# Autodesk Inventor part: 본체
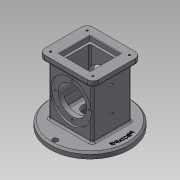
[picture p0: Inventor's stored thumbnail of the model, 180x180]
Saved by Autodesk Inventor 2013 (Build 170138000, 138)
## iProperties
Created: 2019-08
Part Number: 본체
Material: 일반
Document SubType Name: Modeling
Designer: Administrator
Density: 1 g/cm^3
Mass: 384.726 g
Surface Area: 783.782 cm^2
Volume: 384.726 cm^3
Author: Administrator
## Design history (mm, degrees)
sketch "스케치1"
  geometry: C1 r 67.5 at (0, 0); 1 further point
  constraints: 1 centre point, 1 coincident
  dimensions: "d0" = 135 diameter of C1
extrude "돌출1" new body sketch "스케치1" distance "d2" = 10; taper "d3" = 0 deg
sketch "스케치2"
  geometry: L1 (37, -33)-(-37, -33); L2 (-37, -33)-(-37, 33); L3 (-37, 33)-(37, 33); L4 (37, 33)-(37, -33); L5 (37, -33)-(-37, 33); L6 (-37, -33)-(37, 33); C1 r 67.5 at (0, 0) reference
  constraints: 12 end point, 2 midpoint, 2 parallel, 1 horizontal, 1 perpendicular
  dimensions: "d4" = 66 distance of L1.end L2.end; "d6" = 74 distance of L2.end L3.end
extrude "돌출2" join sketch "스케치2" distance "d7" = 98; taper "d8" = 0 deg
sketch "스케치3"
  geometry: L1 (46, -41)-(-46, -41); L2 (-46, -41)-(-46, 41); L3 (-46, 41)-(46, 41); L4 (46, 41)-(46, -41); L5 (46, -41)-(-46, 41); L6 (-46, -41)-(46, 41); 1 further point
  constraints: 12 end point, 2 midpoint, 2 parallel, 1 horizontal, 1 perpendicular
  dimensions: "d9" = 92 distance of L2.end L3.end; "d11" = 82 distance of L3.end L1.start
extrude "돌출3" join sketch "스케치3" distance "d12" = 10; taper "d13" = 0 deg
sketch "스케치4"
  geometry: C1 r 67.5 at (0, 0) reference; C2 r 4.5 at (-59, 0); C3 r 4.5 at (0, 59); C4 r 4.5 at (0, -59); A1 r 59 centre (0, 0) between (-59, 0) and (0, 59)
  constraints: 4 centre point, 3 point on circle, 2 equal radius, 2 vertical alignment, 1 coincident, 1 horizontal alignment
  dimensions: "d14" = 118 diameter of A1; "d16" = 9 diameter of C2
extrude "돌출4" cut sketch "스케치4" stored distance "d17" = 0; taper "d18" = 0 deg
sketch "스케치7"
  geometry: L1 (-33, 98)-(-41, 98) reference; L2 (-41, 98)-(-41, 108) reference; L3 (-41, 108)-(41, 108) reference; L4 (41, 108)-(41, 98) reference; L5 (41, 98)-(33, 98) reference; L6 (33, 98)-(33, 10) reference; L7 (33, 10)-(54.5, 10) reference; L8 (54.5, 10)-(54.5, 0) reference; L9 (54.5, 0)-(-54.5, 0) reference; L10 (-54.5, 0)-(-54.5, 10) reference; L11 (-54.5, 10)-(-33, 10) reference; L12 (-33, 10)-(-33, 98) reference; L13 (-67.5, 0)-(-67.5, 10) reference; L14 (-67.5, 10)-(-63.5, 10) reference; L15 (-63.5, 10)-(-63.5, 0) reference; L16 (-63.5, 0)-(-67.5, 0) reference; L17 (67.5, 10)-(67.5, 0) reference; L18 (67.5, 0)-(63.5, 0) reference; L19 (63.5, 0)-(63.5, 10) reference; L20 (63.5, 10)-(67.5, 10) reference; L21 (-33, 54)-(33, 54); L22 (-33, 89)-(-30, 89); L23 (-30, 89)-(-30, 78); L24 (-30, 78)-(30, 78); L25 (30, 78)-(30, 89); L26 (30, 89)-(33, 89); 1 further point
  constraints: 12 end point, 3 parallel, 2 equal length, 2 midpoint, 2 perpendicular, 2 point on line
  dimensions: "d19" = 70 diameter of L22 L21; "d21" = 48 diameter of L24 L21; "d22" = 3 distance of L22.start L22.end
revolve "회전1" sketch "스케치7" stored, may be unused: angle "d23" = 90 deg
sketch "스케치8"
  geometry: L1 (22, -22)-(-22, -22); L2 (-22, -22)-(-22, 22); L3 (-22, 22)-(22, 22); L4 (22, 22)-(22, -22); L5 (22, -22)-(-22, 22); L6 (-22, -22)-(22, 22); 1 further point
  constraints: 12 end point, 2 midpoint, 2 parallel, 2 perpendicular, 1 horizontal
  dimensions: "d24" = 44 distance of L1.end L2.end
extrude "돌출5" cut sketch "스케치8" distance "d26" = 82; taper "d27" = 0 deg
sketch "스케치9"
  geometry: L1 (26, -26)-(-26, -26); L2 (-26, -26)-(-26, 26); L3 (-26, 26)-(26, 26); L4 (26, 26)-(26, -26); L5 (26, -26)-(-26, 26); L6 (-26, -26)-(26, 26); 1 further point
  constraints: 12 end point, 2 midpoint, 2 parallel, 2 perpendicular, 1 horizontal
  dimensions: "d28" = 52 distance of L1.end L2.end
extrude "돌출6" cut sketch "스케치9" distance "d30" = 8; taper "d31" = 0 deg
sketch "스케치10"
  geometry: L1 (0, 0)-(0, 18); L2 (0, 18)-(-25, 18); L3 (-54.5, 0)-(-54.5, 10) reference; L4 (-54.5, 10)-(-33, 10) reference; L5 (-33, 10)-(-33, 19) reference; L6 (-33, 19)-(-30, 19) reference; L7 (-30, 19)-(-30, 30) reference; L8 (-30, 30)-(-22, 30) reference; L9 (30, 30)-(30, 19) reference; L10 (30, 19)-(33, 19) reference; L11 (33, 19)-(33, 10) reference; L12 (33, 10)-(54.5, 10) reference; L13 (54.5, 10)-(54.5, 0) reference; L14 (54.5, 0)-(-54.5, 0) reference; L15 (41, 98)-(33, 98) reference; L16 (33, 98)-(33, 89) reference; L17 (33, 89)-(30, 89) reference; L18 (30, 89)-(30, 78) reference; L19 (30, 78)-(22, 78) reference; L20 (22, 78)-(22, 100) reference; L21 (22, 100)-(26, 100) reference; L22 (26, 100)-(26, 108) reference; L23 (26, 108)-(41, 108) reference; L24 (41, 108)-(41, 98) reference; L25 (-33, 98)-(-41, 98) reference; L26 (-41, 98)-(-41, 108) reference; L27 (-41, 108)-(-26, 108) reference; L28 (-26, 108)-(-26, 100) reference; L29 (-26, 100)-(-22, 100) reference; L30 (-22, 100)-(-22, 78) reference; L31 (-22, 78)-(-30, 78) reference; L32 (-30, 78)-(-30, 89) reference; L33 (-30, 89)-(-33, 89) reference; L34 (-33, 89)-(-33, 98) reference; L35 (-67.5, 0)-(-67.5, 10) reference; L36 (-67.5, 10)-(-63.5, 10) reference; L37 (-63.5, 10)-(-63.5, 0) reference; L38 (-63.5, 0)-(-67.5, 0) reference; L39 (67.5, 10)-(67.5, 0) reference; L40 (67.5, 0)-(63.5, 0) reference; L41 (63.5, 0)-(63.5, 10) reference; L42 (63.5, 10)-(67.5, 10) reference; L43 (-25, 18)-(-25, 0); L44 (-22, 30)-(-22, 26) reference; L45 (-22, 26)-(22, 26) reference; L46 (22, 26)-(22, 30) reference; L47 (22, 30)-(30, 30) reference
  constraints: 6 end point, 2 perpendicular, 1 point on line, 1 vertical
  dimensions: "d32" = 18 distance of L1.start L1.end; "d33" = 50 diameter of L43 L1
revolve "회전2" sketch "스케치10" stored, may be unused: angle "d34" = 90 deg
sketch "스케치11"
  geometry: L1 (-54.5, 0)-(-54.5, 10) reference; L2 (-54.5, 10)-(-33, 10) reference; L3 (-33, 10)-(-33, 19) reference; L4 (-33, 19)-(-30, 19) reference; L5 (-30, 19)-(-30, 30) reference; L6 (-30, 30)-(-22, 30) reference; L7 (-22, 30)-(-22, 26) reference; L8 (-22, 26)-(22, 26) reference; L9 (22, 26)-(22, 30) reference; L10 (22, 30)-(30, 30) reference; L11 (30, 30)-(30, 19) reference; L12 (30, 19)-(33, 19) reference; L13 (33, 19)-(33, 10) reference; L14 (33, 10)-(54.5, 10) reference; L15 (54.5, 10)-(54.5, 0) reference; L16 (54.5, 0)-(25, 0) reference; L17 (25, 0)-(25, 18) reference; L18 (25, 18)-(-25, 18) reference; L19 (-25, 18)-(-25, 0) reference; L20 (-25, 0)-(-54.5, 0) reference; L21 (41, 98)-(33, 98) reference; L22 (33, 98)-(33, 89) reference; L23 (33, 89)-(30, 89) reference; L24 (30, 89)-(30, 78) reference; L25 (30, 78)-(22, 78) reference; L26 (22, 78)-(22, 100) reference; L27 (22, 100)-(26, 100) reference; L28 (26, 100)-(26, 108) reference; L29 (26, 108)-(41, 108) reference; L30 (41, 108)-(41, 98) reference; L31 (-33, 98)-(-41, 98) reference; L32 (-41, 98)-(-41, 108) reference; L33 (-41, 108)-(-26, 108) reference; L34 (-26, 108)-(-26, 100) reference; L35 (-26, 100)-(-22, 100) reference; L36 (-22, 100)-(-22, 78) reference; L37 (-22, 78)-(-30, 78) reference; L38 (-30, 78)-(-30, 89) reference; L39 (-30, 89)-(-33, 89) reference; L40 (-33, 89)-(-33, 98) reference; L41 (-67.5, 0)-(-67.5, 10) reference; L42 (-67.5, 10)-(-63.5, 10) reference; L43 (-63.5, 10)-(-63.5, 0) reference; L44 (-63.5, 0)-(-67.5, 0) reference; L45 (67.5, 10)-(67.5, 0) reference; L46 (67.5, 0)-(63.5, 0) reference; L47 (63.5, 0)-(63.5, 10) reference; L48 (63.5, 10)-(67.5, 10) reference; L49 (0, 0)-(0, 26); L50 (0, 26)-(-12.5, 26); L51 (-12.5, 26)-(-12.5, 0); L52 (-12.5, 0)-(0, 0)
  constraints: 8 end point, 2 perpendicular, 1 midpoint, 1 point on line
  dimensions: "d35" = 25 diameter of L51 L49
revolve "회전3" sketch "스케치11" stored, may be unused: angle "d37" = 90 deg
sketch "스케치12" dims "d38" = 58
  geometry: C1 r 35 at (0, 0) reference; C2 r 24 at (0, 0) reference; 3 further points
  constraints: 2 vertical alignment, 1 coincident, 2 other
hole "구멍1" sketch "스케치12" at (0, 29) diameter "d40" = 3.242; stored, may be unused: countersink angle "d44" = 90 deg, drill point angle "d46" = 118 deg; dims "d41" = 4, "d42" = 4, "d43" = 2, "d45" = 6
sketch "스케치13"
  geometry: L1 (36, -31)-(-36, -31); L2 (-36, -31)-(-36, 31); L3 (-36, 31)-(36, 31); L4 (36, 31)-(36, -31); L5 (36, -31)-(-36, 31); L6 (-36, -31)-(36, 31); 5 further points
  constraints: 12 end point, 4 coincident, 2 midpoint, 2 parallel, 1 horizontal, 1 perpendicular
  dimensions: "d50" = 62 distance of L1.end L2.end; "d52" = 72 distance of L2.end L3.end
hole "구멍2" sketch "스케치13" at (-36, 31), (36, -31), (36, 31), (-36, -31) diameter "d53" = 3.242; stored, may be unused: countersink angle "d57" = 90 deg, drill point angle "d59" = 118 deg; dims "d54" = 4, "d55" = 4, "d56" = 2, "d58" = 6
sketch "스케치14"
  geometry: L1 (0, 89.456)-(10, 89.456) reference; L2 (10, 89.456)-(10, -23.456) reference; L3 (10, -23.456)-(0, -23.456) reference; L4 (0, -23.456)-(0, 0) reference; L5 (0, 0)-(0, 66) reference; L6 (0, 66)-(0, 89.456) reference; L7 (0, 0)-(-88, 0) reference; L8 (-88, 0)-(-88, -8) reference; L9 (-88, -8)-(-98, -8) reference; L10 (-98, -8)-(-98, 0.724) reference; L11 (-98, 74)-(-88, 74) reference; L12 (-88, 74)-(-88, 66) reference; L13 (-88, 66)-(-88, 0) reference; L14 (-88, 66)-(0, 66) reference; L15 (-98, 0.724)-(-92, 0.724) reference; L16 (-92, 3.276)-(-98, 3.276) reference; L17 (-98, 3.276)-(-98, 62.724) reference; L18 (-98, 62.724)-(-92, 62.724) reference; L19 (-92, 65.276)-(-98, 65.276) reference; L20 (-98, 65.276)-(-98, 74) reference; 4 further points
  constraints: 2 horizontal alignment, 2 vertical alignment, 1 midpoint
  dimensions: "d60" = 37 distance from line of L2 point (-27, 33); "d61" = 43 distance of point (-27, 33) point (-70, 33)
hole "구멍3" sketch "스케치14" at (-27, 33), (-70, 33) diameter "d62" = 4.917; stored, may be unused: countersink angle "d66" = 90 deg, drill point angle "d68" = 118 deg; dims "d63" = 4, "d64" = 4, "d65" = 2, "d67" = 30
fillet "모깎기2" dims "d70" = 3
fillet "모깎기3" dims "d71" = 3
fillet "모깎기4" dims "d72" = 10
fillet "모깎기5" dims "d73" = 3
fillet "모깎기6" dims "d74" = 3
chamfer "모따기1" distance "d75" = 1; stored, may be unused: second distance "d76" = 2, angle "d77" = 45 deg
fillet "모깎기7" dims "d78" = 3
fillet "모깎기8" dims "d79" = 3
node "작업 평면1"
fillet "모깎기9" dims "d84" = 3
chamfer "모따기2" distance "d85" = 3; stored, may be unused: second distance "d86" = 2, angle "d87" = 45 deg
sketch "스케치16"
  geometry: C1 r 64.5 at (0, 0) reference; C2 r 59 at (0, 0)
  constraints: 1 centre point, 1 coincident, 1 other
  dimensions: "d90" = 118 diameter of C2
feature "엠보싱2" sketch "스케치16" dims "d2" = 10, "d92" = 0.5, "d93" = 0
node "솔리드1"
pattern_circular "원형 패턴1" dims angle "d48" = 360 deg
mirror "대칭1"
node "절단 모서리 투영2"
node "절단 모서리 투영3"
node "절단 모서리 투영4"
node "절단 모서리 투영5"
